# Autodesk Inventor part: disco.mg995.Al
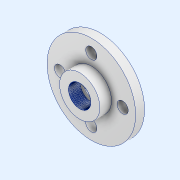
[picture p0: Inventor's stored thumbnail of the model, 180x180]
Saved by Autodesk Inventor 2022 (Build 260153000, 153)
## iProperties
Created: 2020-10
Part Number: disco.mg995.Al
Material: Generico
Document SubType Name: Modeling
Designer: admin
Density: 1 g/cm^3
Appearance: Alluminio - Piatto
Author: admin
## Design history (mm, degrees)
sketch "Schizzo1"
  geometry: C1 r 9.9 at (0, 0); 1 further point
  constraints: 1 centre point, 1 coincident
  dimensions: "d0" = 19.8 diameter of C1
extrude "Estrusione1" new body sketch "Schizzo1" distance "d1" = 2; taper "d2" = 0 deg
sketch "Schizzo2"
  geometry: C1 r 4.5 at (0, 0); 1 further point
  constraints: 1 centre point, 1 coincident
  dimensions: "d3" = 9 diameter of C1
extrude "Estrusione2" join sketch "Schizzo2" distance "d4" = 2.6; taper "d5" = 0 deg
sketch "Schizzo3" dims "d6" = 14
  geometry: C1 r 1.25 at (0, 7); 2 further points
  constraints: 1 centre point, 1 coincident, 1 vertical alignment, 2 other
  dimensions: "d7" = 2.5 diameter of C1
extrude "Estrusione3" cut sketch "Schizzo3" distance "d8" = 2.5; taper "d9" = 0 deg
node "Asse di lavoro1"
pattern_circular "Serie circolare1" dims angle "d11" = 360 deg
sketch "Schizzo4"
  geometry: C1 r 2.5 at (0, 0); 1 further point
  constraints: 1 centre point, 1 coincident
  dimensions: "d13" = 5 diameter of C1
extrude "Estrusione4" cut sketch "Schizzo4" extent not by distance; stored distance "d14" = 0; taper "d15" = 0 deg
sketch "Schizzo5"
  geometry: C1 r 2.5 at (0, 0) reference; C2 r 1.6 at (0, 0); 1 further point
  constraints: 1 centre point, 1 coincident
  dimensions: "d16" = 3.2 diameter of C2
extrude "Estrusione5" join sketch "Schizzo5" distance "d17" = 2; taper "d18" = 0 deg
sketch "Schizzo6"
  geometry: L1 (0.024, -2.498)-(-0.024, -2.498); L2 (0, -2.518)-(0, -2.401); L3 (-0.024, -2.498)-(-0.036, -2.498); L4 (-0.036, -2.498)-(-0.069, -2.498); L5 (-0.069, -2.498)-(0, -2.429); L6 (0.036, -2.498)-(0.069, -2.498); L7 (0.069, -2.498)-(0, -2.429); L8 (0.069, -2.498)-(0.067, -2.498); L9 (0.024, -2.498)-(0.032, -2.498); L10 (0.032, -2.498)-(0.069, -2.498); C1 r 2.5 at (0, 0) reference; 2 further points
  constraints: 20 end point, 2 point on line, 2 symmetric about line, 1 collinear, 1 horizontal, 1 vertical
extrude "Estrusione6" join sketch "Schizzo6" stored distance "d20" = 2; taper "d21" = 0 deg
node "Solido1"
pattern_circular "Serie circolare2" dims angle "d23" = 360 deg
